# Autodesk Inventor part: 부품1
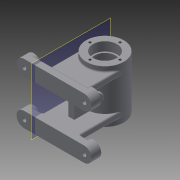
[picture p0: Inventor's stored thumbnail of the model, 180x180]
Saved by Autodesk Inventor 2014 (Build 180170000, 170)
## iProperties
Created: 2015-11
Part Number: 부품1
Material: 일반
Document SubType Name: Modeling
Designer: Owner
Density: 1 g/cm^3
Appearance: 기본값
Author: Owner
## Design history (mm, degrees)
sketch "스케치1"
  geometry: C1 r 25 at (0, 0); 1 further point
  constraints: 1 centre point, 1 coincident
  dimensions: "d0" = 50 diameter of C1
extrude "돌출1" new body sketch "스케치1" distance "d1" = 70; taper "d2" = 0 deg
sketch "스케치2"
  geometry: L1 (25, 70)-(25, 0) reference; L2 (25, 0)-(-25, 0) reference; L3 (-25, 0)-(-25, 70) reference; L4 (-25, 70)-(25, 70) reference; L5 (0, 70)-(0, 0); L6 (16, 70)-(16, 58.3); L7 (15.7, 58)-(14, 58); L8 (14, 58)-(14, 56); L9 (14, 56)-(18, 56); L10 (21, 53)-(21, 17); L11 (18, 14)-(14, 14); L12 (14, 14)-(14, 12); L13 (14, 12)-(15.7, 12); L14 (16, 11.7)-(16, 0); L15 (16, 70)-(0, 70); L16 (16, 0)-(0, 0); A1 r 3 centre (18, 53) between (21, 53) and (18, 56); A2 r 3 centre (18, 17) between (18, 14) and (21, 17); A3 r 0.3 centre (15.7, 11.7) between (16, 11.7) and (15.7, 12); A4 r 0.3 centre (15.7, 58.3) between (15.7, 58) and (16, 58.3); 4 further points
  constraints: 24 end point, 10 point on line, 8 point on circle, 8 tangent, 7 parallel, 4 centre point, 4 perpendicular, 1 equal radius, 1 midpoint, 1 vertical
  dimensions: "d3" = 12 distance of L6.start point (16, 58); "d5" = 32 diameter of L6 L5; "d6" = 2 distance of L7.end L8.end; "d7" = 28 diameter of L8 L5; "d8" = 42 diameter of L10 L5; "d9" = 42 distance of point (21, 56) point (21, 14); "d10" = 3 radius of A1; "d11" = 12 distance of point (16, 12) L14.end; "d12" = 32 diameter of L14 L5; "d13" = 28 diameter of L12 L5; "d14" = 3 radius of A2; "d15" = 0.3 radius of A3
revolve "회전1" sketch "스케치2" stored, may be unused: angle "d16" = 90 deg
node "작업 평면2"
  node "작업 평면1"
sketch "스케치3"
  geometry: L1 (25, 70)-(-25, 70) reference; L2 (-25, 0)-(25, 0) reference; L3 (25, 0)-(25, 70) reference; L4 (-25, 0)-(-25, 70) reference; L5 (40, 75)-(-40, 75); L6 (-40, 75)-(-40, 55); L7 (-40, 55)-(40, 55); L8 (40, 55)-(40, 75); L9 (23.393, 15)-(-5.047, 15); L10 (-5.047, -5)-(23.393, -5); L11 (-25, 35)-(-19.624, 35); L12 (0, 0)-(0, 2.808); L13 (23.393, 15)-(40, 15); L14 (40, -5)-(23.393, -5); L15 (-5.047, -5)-(-40, -5); L16 (-5.047, 15)-(-40, 15); A1 r 10 centre (-40, 65) between (-40, 75) and (-40, 55); A2 r 10 centre (40, 65) between (40, 55) and (40, 75); A3 r 10 centre (40, 5) between (40, -5) and (40, 15); A4 r 10 centre (-40, 5) between (-40, 15) and (-40, -5)
  constraints: 24 end point, 8 point on circle, 7 symmetric about line, 4 centre point, 3 midpoint, 3 parallel, 2 horizontal, 2 perpendicular, 2 tangent, 1 collinear, 5 other
  dimensions: "d20" = 80 distance between parallel lines of L10 L5; "d21" = 20 distance of L7.end L5.start; "d22" = 80 distance of L6.end L7.end; "d23" = 20 distance between parallel lines of L10 L9
  node "투영된 루프1"
sketch "스케치4" dims "d24" = 40
  geometry: C1 r 16 at (0, 0) reference; C2 r 25 at (0, 0) reference; 2 further points
  constraints: 2 vertical alignment, 1 coincident, 2 other
hole "구멍1" sketch "스케치4" at (0, 20) diameter "d25" = 3.242; stored, may be unused: countersink angle "d29" = 90 deg, drill point angle "d31" = 118 deg; dims "d26" = 6, "d27" = 4, "d28" = 2, "d30" = 8
extrude "돌출2" join sketch "스케치3" distance "d32" = 10; taper "d33" = 0 deg
node "작업 평면3"
sketch "스케치5"
  geometry: C1 r 10 at (-40, -65); C2 r 10 at (40, -65); A1 r 10 centre (40, -65) between (40, -75) and (40, -55) reference; A2 r 10 centre (-40, -65) between (-40, -55) and (-40, -75) reference; 1 further point
  constraints: 2 centre point, 2 coincident, 2 concentric
extrude "돌출3" join sketch "스케치5" distance "d37" = 3; taper "d38" = 0 deg
sketch "스케치6"
  geometry: C1 r 10 at (0, 0) reference; C2 r 10 at (80, 0) reference; 1 further point
hole "구멍2" sketch "스케치6" at (0, 0), (80, 0) diameter "d39" = 6; stored, may be unused: countersink angle "d43" = 90 deg, drill point angle "d45" = 0 deg; dims "d40" = 6, "d41" = 12, "d42" = 4, "d44" = 13
fillet "모깎기1" dims "d46" = 0.3
chamfer "모따기1" distance "d47" = 1; stored, may be unused: second distance "d48" = 2, angle "d49" = 45 deg
sketch "스케치7"
  geometry: L1 (40, -55)-(-40, -55) reference; L2 (25, -63)-(-25, -63); L3 (-25, -63)-(-25, -55); L4 (-25, -55)-(25, -55); L5 (25, -55)-(25, -63); 2 further points
  constraints: 8 end point, 2 midpoint, 2 parallel, 1 horizontal, 1 perpendicular, 1 vertical alignment
  dimensions: "d50" = 8 distance of L4.end L2.start; "d51" = 50 distance of L3.end L4.end
extrude "돌출4" join sketch "스케치7" stored distance "d52" = 3; taper "d53" = 0 deg
node "작업 평면4"
sketch "스케치8"
  geometry: L1 (63, 74)-(51.3, 74) reference; L2 (51, 73.7)-(51, 72) reference; L3 (51, 72)-(49, 72) reference; L4 (49, 72)-(49, 76) reference; L5 (46, 79)-(10, 79) reference; L6 (7, 76)-(7, 72) reference; L7 (7, 72)-(5, 72) reference; L8 (5, 72)-(5, 73.7) reference; L9 (4.7, 74)-(-7, 74) reference; L10 (-7, 74)-(-7, 76.379) reference; L11 (-7, 76.379)-(1, 76.379) reference; L12 (1, 76.379)-(1.974, 78) reference; L13 (1.974, 78)-(1, 79.621) reference; L14 (1, 79.621)-(-7, 79.621) reference; L15 (-7, 79.621)-(-7, 83) reference; L16 (-7, 83)-(63, 83) reference; L17 (63, 83)-(63, 79.621) reference; L18 (63, 79.621)-(55, 79.621) reference; L19 (55, 79.621)-(54.026, 78) reference; L20 (54.026, 78)-(55, 76.379) reference; L21 (55, 76.379)-(63, 76.379) reference; L22 (63, 76.379)-(63, 74) reference; L23 (51.3, 42)-(63, 42) reference; L24 (63, 42)-(63, 39.621) reference; L25 (63, 39.621)-(55, 39.621) reference; L26 (55, 39.621)-(54.026, 38) reference; L27 (54.026, 38)-(55, 36.379) reference; L28 (55, 36.379)-(63, 36.379) reference; L29 (63, 36.379)-(63, 33) reference; L30 (63, 33)-(56, 33) reference; L31 (56, 33)-(56, 0) reference; L32 (56, 0)-(68, 0) reference; L33 (68, 0)-(68, -10) reference; L34 (68, -10)-(48, -10) reference; L35 (48, -10)-(48, 33) reference; L36 (48, 33)-(8, 33) reference; L37 (8, 33)-(8, -10) reference; L38 (8, -10)-(-12, -10) reference; L39 (-12, -10)-(-12, 0) reference; L40 (-12, 0)-(0, 0) reference; L41 (0, 0)-(0, 33) reference; L42 (0, 33)-(-7, 33) reference; L43 (-7, 33)-(-7, 36.379) reference; L44 (-7, 36.379)-(1, 36.379) reference; L45 (1, 36.379)-(1.974, 38) reference; L46 (1.974, 38)-(1, 39.621) reference; L47 (1, 39.621)-(-7, 39.621) reference; L48 (-7, 39.621)-(-7, 42) reference; L49 (-7, 42)-(4.7, 42) reference; L50 (5, 42.3)-(5, 44) reference; L51 (5, 44)-(7, 44) reference; L52 (7, 44)-(7, 40) reference; L53 (10, 37)-(46, 37) reference; L54 (49, 40)-(49, 44) reference; L55 (49, 44)-(51, 44) reference; L56 (51, 44)-(51, 42.3) reference; L57 (8, 13)-(48, 13); L58 (48, 13)-(8, 13); L59 (8, 13)-(8, 33); L60 (8, 33)-(48, 33); L61 (48, 33)-(48, 13); A1 r 0.3 centre (51.3, 73.7) between (51.3, 74) and (51, 73.7) reference; A2 r 3 centre (46, 76) between (49, 76) and (46, 79) reference; A3 r 3 centre (10, 76) between (10, 79) and (7, 76) reference; A4 r 0.3 centre (4.7, 73.7) between (5, 73.7) and (4.7, 74) reference; A5 r 0.3 centre (4.7, 42.3) between (4.7, 42) and (5, 42.3) reference; A6 r 3 centre (10, 40) between (7, 40) and (10, 37) reference; A7 r 3 centre (46, 40) between (46, 37) and (49, 40) reference; A8 r 0.3 centre (51.3, 42.3) between (51, 42.3) and (51.3, 42) reference; 1 further point
  constraints: 10 end point, 2 parallel, 2 perpendicular, 2 point on line, 1 horizontal
  dimensions: "d60" = 20 distance between parallel lines of L58 L36
extrude "돌출5" join sketch "스케치8" stored distance "d55" = 8; taper "d56" = 0 deg
sketch "스케치9"
  geometry: L1 (8, 13)-(48, 13) reference; L2 (48, 33)-(8, 33) reference; L3 (28, 33)-(28, 13); L4 (61, -10)-(55, -10) reference; L5 (20, 26.5)-(36, 26.5); L6 (36, 19.5)-(20, 19.5); A1 r 3.5 centre (20, 23) between (20, 26.5) and (20, 19.5); A2 r 3.5 centre (36, 23) between (36, 19.5) and (36, 26.5); 1 further point
  constraints: 6 end point, 4 point on circle, 2 centre point, 2 midpoint, 2 tangent, 1 equal radius, 1 horizontal, 1 parallel, 1 other
  dimensions: "d57" = 7 diameter of A1; "d58" = 23 dimension on A2 A1; "d59" = 33 distance from line of L4 A2.centre
extrude "돌출6" cut sketch "스케치9" stored distance "d61" = 8; taper "d62" = 0 deg
node "작업 평면6"
  node "작업 평면5"
sketch "스케치10"
  geometry: L1 (-25, 7)-(-25, 15) reference; L2 (-25, 15)-(0, 15) reference; L3 (0, 15)-(0, 55) reference; L4 (0, 55)-(-25, 55) reference; L5 (-25, 55)-(-25, 63) reference; L6 (-25, 63)-(25, 63) reference; L7 (25, 55)-(25, 63) reference; L8 (25, 55)-(0, 55) reference; L9 (0, 15)-(25, 15) reference; L10 (25, 7)-(25, 15) reference; L11 (25, 7)-(-25, 7) reference; L12 (25, 70)-(-25, 70) reference; L13 (-25, 0)-(25, 0) reference; C1 r 5 at (0, 35); 1 further point
  constraints: 1 centre point, 1 midpoint
  dimensions: "d64" = 10 diameter of C1
extrude "돌출7" join sketch "스케치10" stored distance "d65" = 8; taper "d66" = 0 deg
sketch "스케치11"
  geometry: C1 r 5 at (0, 0) reference; 1 further point
hole "구멍3" sketch "스케치11" at (0, 0) diameter "d67" = 5.188; stored, may be unused: countersink angle "d71" = 90 deg, drill point angle "d73" = 0 deg; dims "d68" = 6, "d69" = 12, "d70" = 4, "d72" = 13
sketch "스케치13"
  geometry: L1 (0, 0)-(0, -47.58); L2 (0, 0)-(16.166, -28); C1 r 1.621 at (20, 0) reference; C2 r 1.621 at (0, -20) reference; C3 r 1.621 at (-20, 0) reference; C4 r 1.621 at (0, 20) reference; C5 r 16 at (0, 0) reference; 1 further point
  constraints: 4 end point, 1 point on line, 1 vertical, 2 other
  dimensions: "d77" = 30 deg angle of L2 L1; "d78" = 28 vertical distance of L1.start L2.end
node "작업 평면7"
sketch "스케치14"
  geometry: L1 (-9.815, -15)-(-9.815, -55) reference; L2 (-9.815, -55)-(0, -55) reference; L3 (0, -55)-(0, -15) reference; L4 (14.434, -15)-(0, -15) reference; L5 (14.434, -7)-(14.434, -15) reference; L6 (0, -7)-(14.434, -7) reference; L7 (0, -7)-(0, 0) reference; L8 (0, -15)-(-9.815, -15) reference; L9 (0, -55)-(14.434, -55) reference; L10 (14.434, -55)-(14.434, -63) reference; L11 (14.434, -63)-(0, -63) reference; L12 (0, -70)-(0, -63) reference; L13 (-43.301, -7)-(0, -7) reference; L14 (-43.301, -15)-(-43.301, -7) reference; L15 (-19.053, -15)-(-43.301, -15) reference; L16 (-19.053, -55)-(-19.053, -15) reference; L17 (-43.301, -55)-(-19.053, -55) reference; L18 (-43.301, -63)-(-43.301, -55) reference; L19 (0, -63)-(-43.301, -63) reference; L20 (-66.699, -7.881)-(-66.699, -13.503) reference; L21 (-66.699, 3.503)-(-66.699, -2.119) reference; L22 (-66.699, -67.881)-(-66.699, -73.503) reference; L23 (-66.699, -56.497)-(-66.699, -62.119) reference; C1 r 6 at (0, -35); 4 further points; 4 other entities
  constraints: 1 centre point, 1 midpoint, 4 other
  dimensions: "d79" = 12 diameter of C1
extrude "돌출8" join sketch "스케치14" distance "d80" = 3; taper "d81" = 0 deg
sketch "스케치15"
  geometry: C1 r 6 at (0, 0) reference; 1 further point
hole "구멍4" sketch "스케치15" at (0, 0) diameter "d82" = 5.188; stored, may be unused: countersink angle "d86" = 90 deg, drill point angle "d88" = 0 deg; dims "d83" = 6, "d84" = 12, "d85" = 4, "d87" = 13
fillet "모깎기2" dims "d89" = 2
fillet "모깎기3" dims "d90" = 2
fillet "모깎기4" dims "d91" = 2
node "작업 평면9"
  node "작업 평면8"
sketch "스케치16"
  geometry: 1 further point
sketch "스케치17"
  geometry: L1 (-25, -146.365)-(-25, 216.365); L2 (-25, 216.365)-(25, 216.365); L3 (25, 216.365)-(25, -146.365); L4 (25, -146.365)-(-25, -146.365); L5 (59.708, 15)-(68, 15) reference; L6 (68, 15)-(68, -5) reference; L7 (68, -5)-(60, -5) reference; L8 (58, -3)-(58, 5) reference; L9 (57.323, 8)-(57.323, 13) reference; L10 (58, 65)-(58, 73) reference; L11 (60, 75)-(68, 75) reference; L12 (68, 75)-(68, 55) reference; L13 (68, 55)-(59.708, 55) reference; L14 (57.323, 57)-(57.323, 62) reference; L15 (-25, 0)-(-25, 70) reference; L16 (25, 70)-(-25, 70) reference; L17 (-25, 0)-(25, 0) reference; A1 r 2 centre (60, -3) between (58, -3) and (60, -5) reference; A2 r 2 centre (56, 5) between (58, 5) and (57.854, 5.75) reference; A3 r 2 centre (60, 73) between (60, 75) and (58, 73) reference; A4 r 2 centre (56, 65) between (57.854, 64.25) and (58, 65) reference; 8 further points
  constraints: 7 midpoint, 2 vertical alignment, 1 coincident, 1 horizontal alignment, 6 other
extrude "돌출9" join sketch "스케치17" distance "d93" = 0.5; taper "d94" = 0 deg
node "솔리드1"
pattern_circular "원형 패턴1" dims angle "d35" = 360 deg
mirror "대칭1"
mirror "대칭2"
mirror "대칭3"
node "투영된 루프2"
node "절단 모서리 투영1"
node "절단 모서리 투영2"
node "절단 모서리 투영3"
node "절단 모서리 투영4"
other parameters: "d17" = -43, "d63" = -3, "d92" = -0.5
